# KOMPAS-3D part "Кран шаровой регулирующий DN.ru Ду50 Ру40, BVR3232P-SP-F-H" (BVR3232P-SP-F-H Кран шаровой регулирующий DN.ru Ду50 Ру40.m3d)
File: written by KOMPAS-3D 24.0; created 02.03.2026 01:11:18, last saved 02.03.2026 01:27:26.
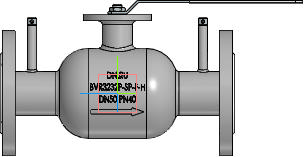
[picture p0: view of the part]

Document properties: Автор: Максим; Полное имя файла: BVR3232P-SP-F-H - Кран шаровой регулирующий DN.ru  Ду50 Ру40.cdw

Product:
- Body: Тело 1  | qty 1
    Масса: 17.137612
- Part/product: Кран шаровой регулирующий DN.ru Ду50 Ру40  | designation BVR3232P-SP-F-H
    Масса: 10.6
    Раздел спецификации: Прочие изделия
    Форматы листов документа: A3
    Примечание: D160-28454

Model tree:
1. Операция без истории:1

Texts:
  BVR3232P-SP-F-H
